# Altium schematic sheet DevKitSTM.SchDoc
size A2; PageSetup: Record=PageOptions¦CenterHorizontal=True¦CenterVertical=True¦PrintScale=0.52¦XCorrection=1.00¦YCorrection=1.00¦PrintKind=1¦BorderSize=5000000¦LeftOffset=0¦BottomOffset=0¦Orientation=2¦PaperLength=1000¦PaperWidth=1000¦Scale=100¦PaperSource=7¦PrintQuality=600¦MediaType=1¦DitherType=10¦PaperKind=A4¦PrintScaleMode=1
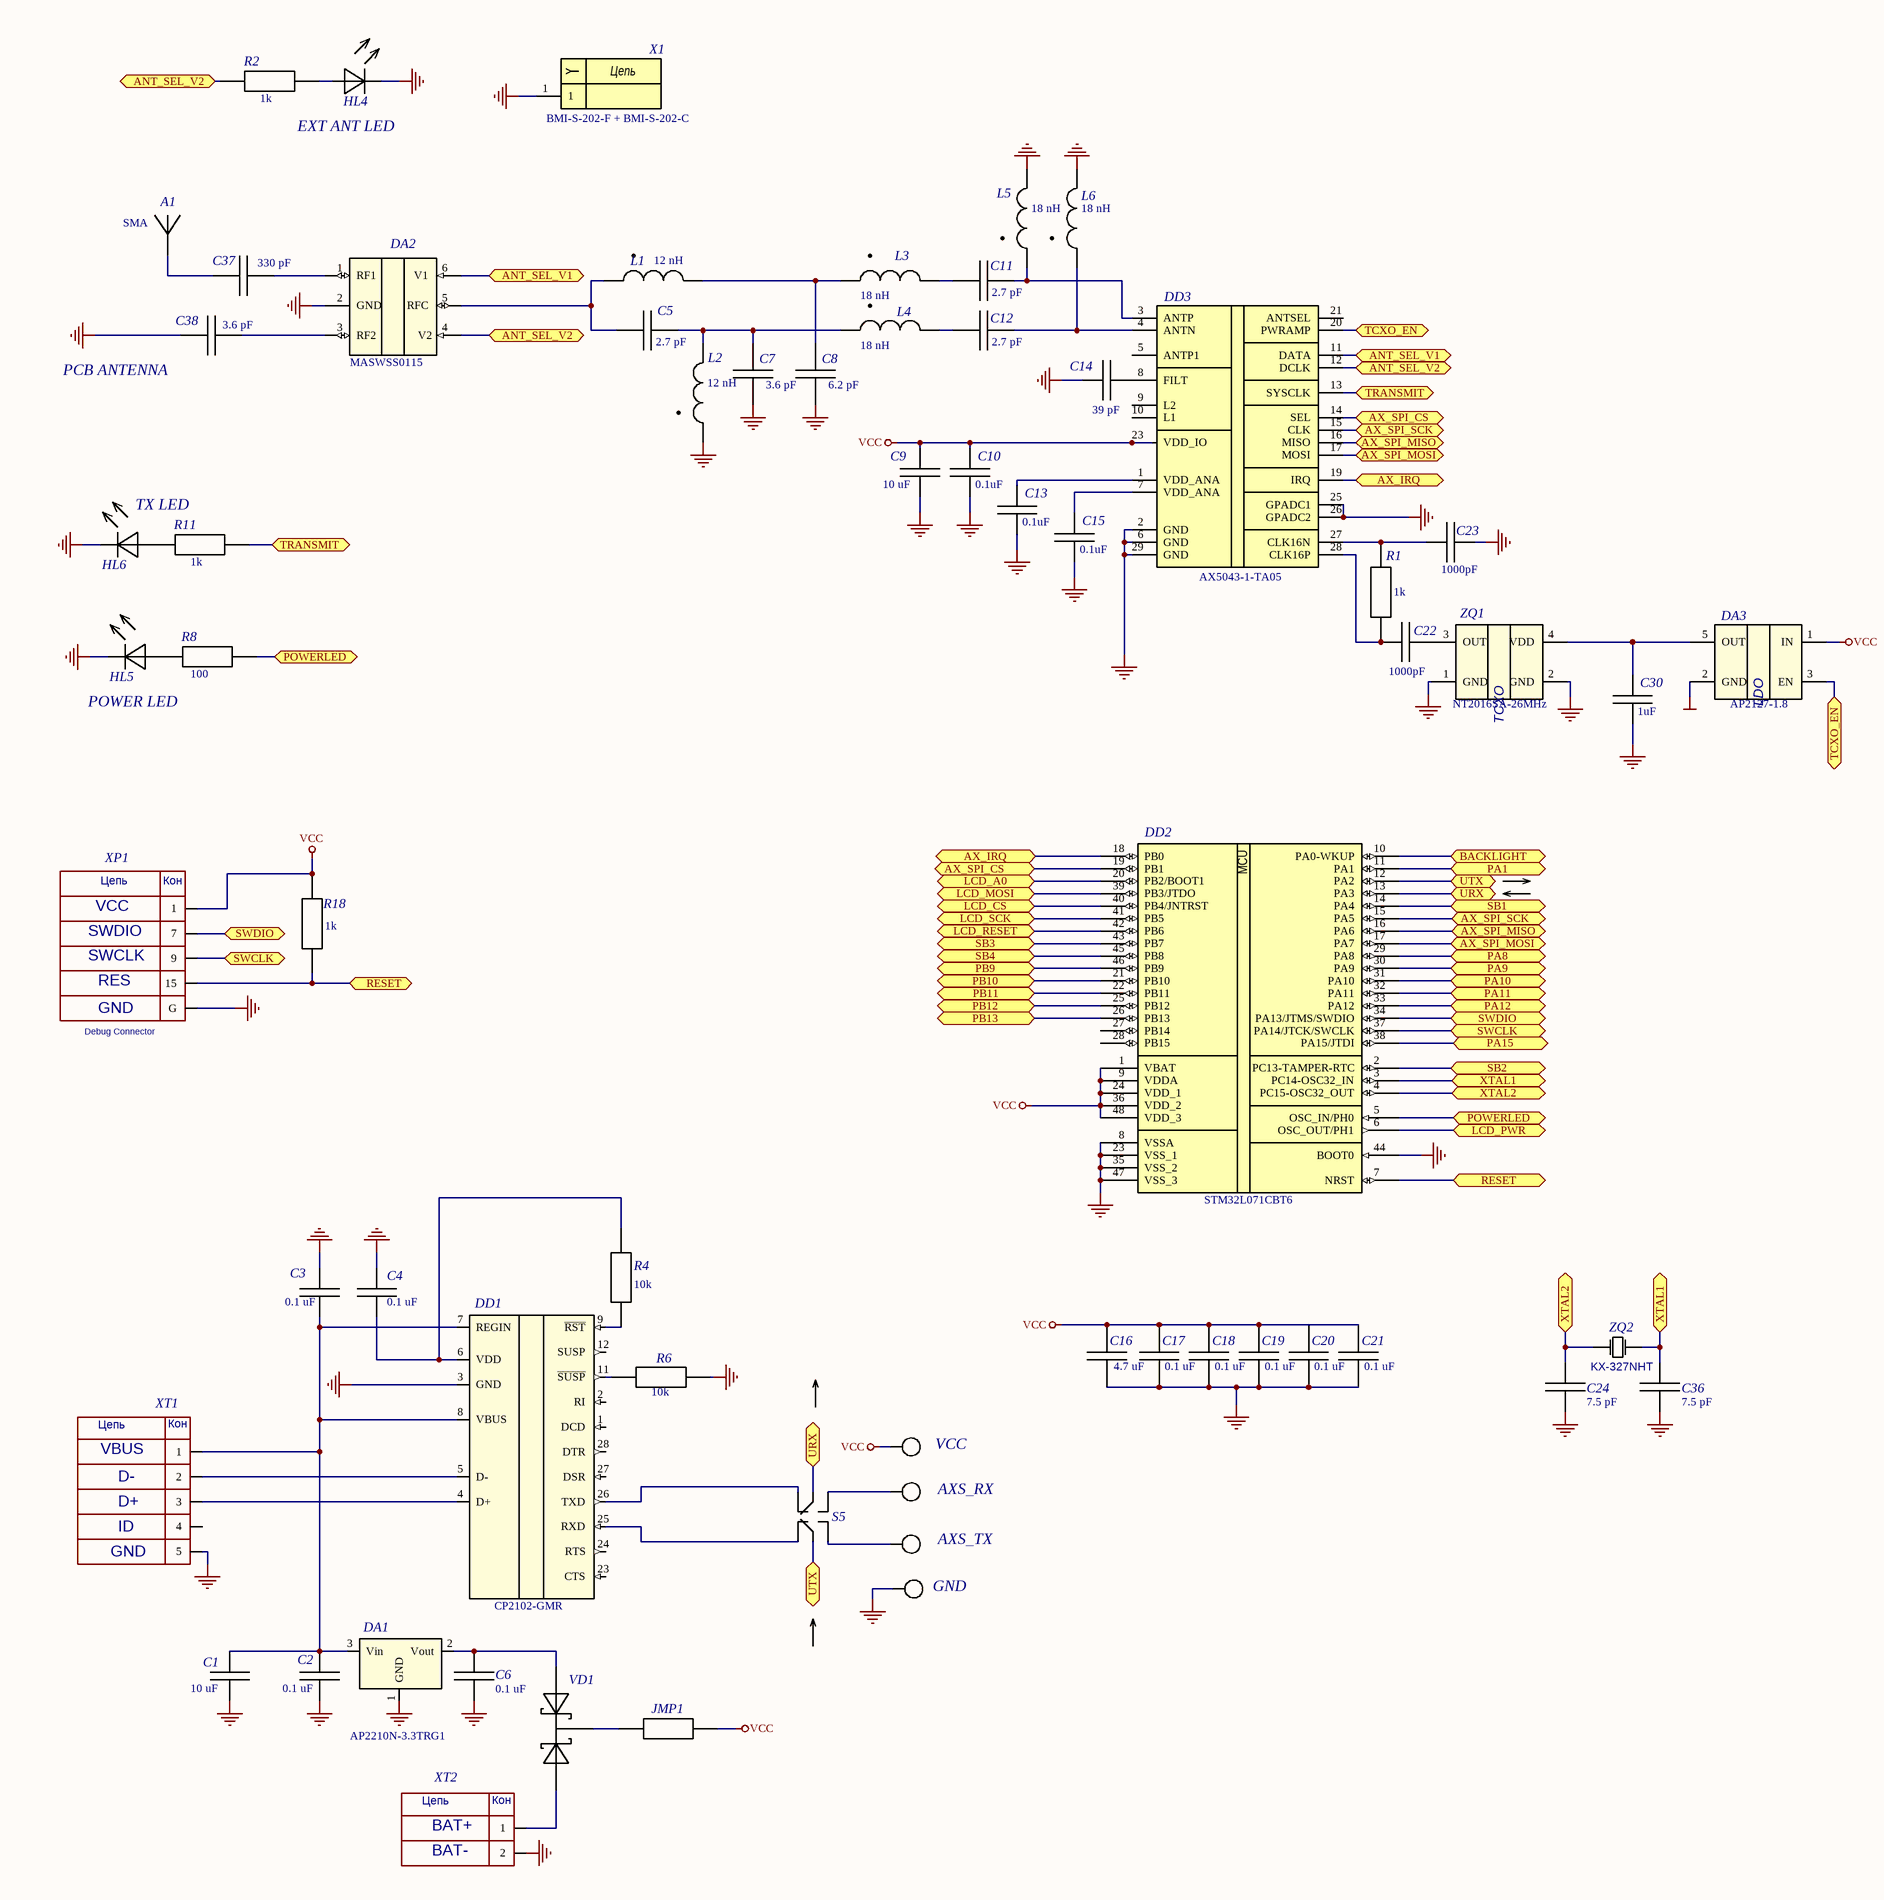
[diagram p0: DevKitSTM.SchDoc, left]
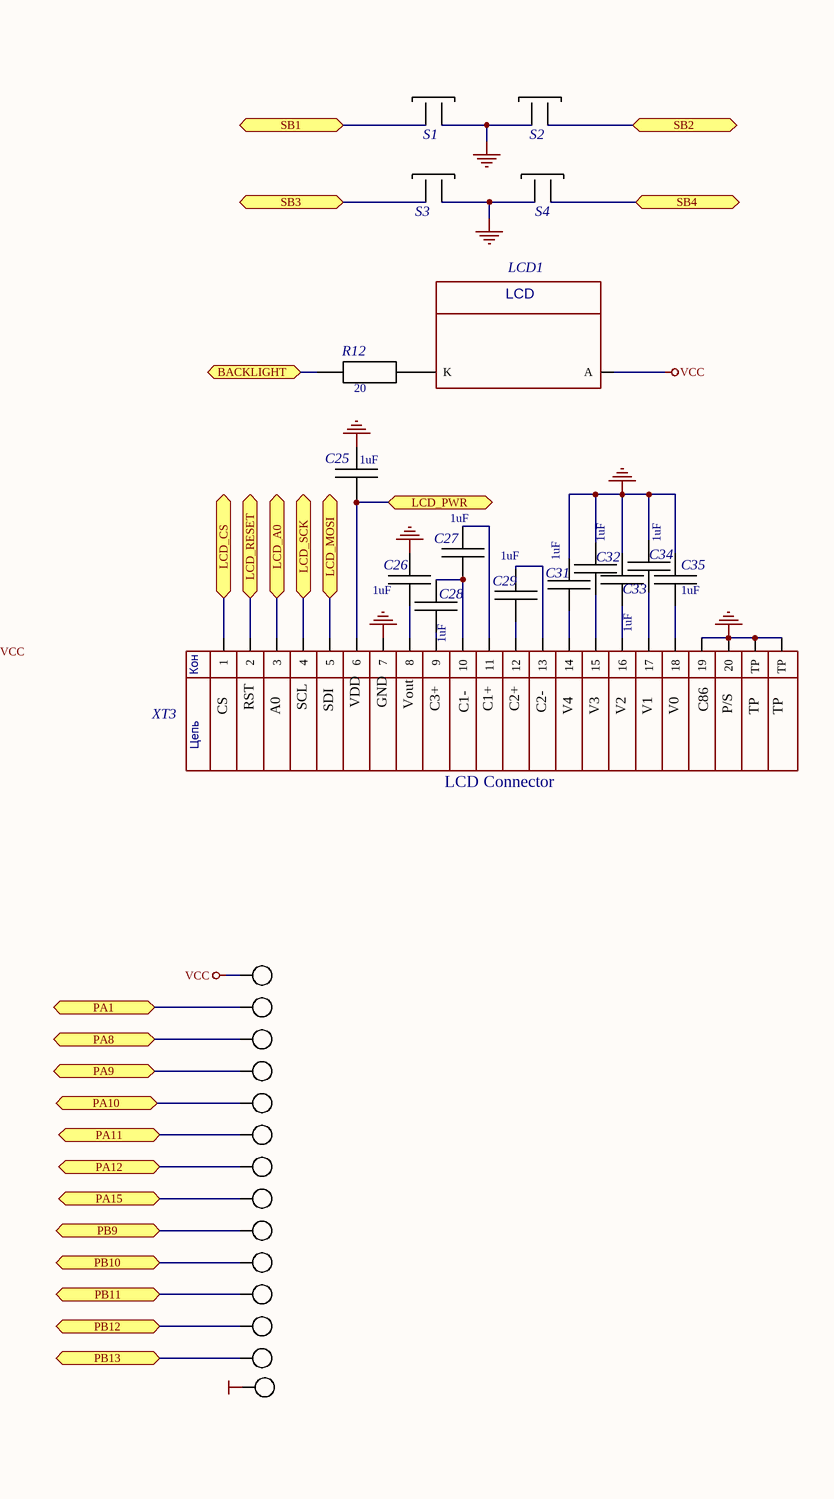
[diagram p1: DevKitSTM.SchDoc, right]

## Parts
A1  SMA  [SMA_Str]  (net tie, no BOM)
C1  10 uF  [Cap_1206]
C2  0.1 uF  [Cap_0603]
C3  0.1 uF  [Cap_0603]
C4  0.1 uF  [Cap_0603]
C5  value 2.7 pF  [CAP_0603]
C6  0.1 uF  [Cap_0603]
C7  value 3.6 pF  [CAP_0603]
C8  value 6.2 pF  [CAP_0603]
C9  10 uF  [Cap_1206]
C10  0.1uF  [Cap_0603]
C11  value 2.7 pF  [CAP_0603]
C12  value 2.7 pF  [CAP_0603]
C13  0.1uF  [Cap_0603]
C14  39 pF  [Cap_0603]
C15  0.1uF  [Cap_0603]
C16  value 4.7 uF  [CAP_0603]
C17  value 0.1 uF  [CAP_0603]
C18  value 0.1 uF  [CAP_0603]
C19  value 0.1 uF  [CAP_0603]
C20  value 0.1 uF  [CAP_0603]
C21  value 0.1 uF  [CAP_0603]
C22  1000pF  [Cap_0603]
C23  1000pF  [Cap_0603]
C24  7.5 pF  [Cap_0603]
C25  1uF  [Cap_0603]
C26  1uF  [Cap_0603]
C27  1uF  [Cap_0603]
C28  1uF  [Cap_0603]
C29  1uF  [Cap_0603]
C30  1uF  [Cap_0603]
C31  1uF  [Cap_0603]
C32  1uF  [Cap_0603]
C33  1uF  [Cap_0603]
C34  1uF  [Cap_0603]
C35  1uF  [Cap_0603]
C36  7.5 pF  [Cap_0603]
C37  value 330 pF  [CAP_0603]
C38  value 3.6 pF  [CAP_0603]
DA1  PartNumber: AP2210N-3.3TRG1  [SOT23_L]  (hidden comment: AP2210)
DA2  MASWSS0115  [SC-70]
DA3  AP2127-1.8  [SOT23-5AN]
DD1  PartNumber: CP2102-GMR  [QFN28]  (hidden comment: CP2102)
DD2  STM32L071CBT6  [TSQFP50P900X900X160-48N]
DD3  AX5043-1-TA05  [QFN28]
HL4  LED_0603  [led0603]  (value not drawn)
HL5  LED_0603  [led0603]  (value not drawn)
HL6  LED_0603  [led0603]  (value not drawn)
JMP1  STD_RES  [JMP_PCB]  (value not drawn)  (no BOM)
L1  value 12 nH  [IND_0603]  (hidden comment: STD_IND)
L2  value 12 nH  [IND_0603]  (hidden comment: STD_IND)
L3  value 18 nH  [IND_0603]  (hidden comment: STD_IND)
L4  value 18 nH  [IND_0603]  (hidden comment: STD_IND)
L5  value 18 nH  [IND_0603]  (hidden comment: STD_IND)
L6  value 18 nH  [IND_0603]  (hidden comment: STD_IND)
LCD1  LCD_JHD  [LCD_JHD]  (value not drawn)
R1  1k  [RES_0603]
R2  1k  [RES_0603]
R4  10k  [RES_0603]
R6  10k  [RES_0603]
R8  100  [RES_0603]
R11  1k  [RES_0603]
R12  20  [RES_0603]
R18  1k  [RES_0603]
S1  SMD Button  [FSM_Button]  (value not drawn)  (no BOM)
S2  SMD Button  [FSM_Button]  (value not drawn)  (no BOM)
S3  SMD Button  [FSM_Button]  (value not drawn)  (no BOM)
S4  SMD Button  [FSM_Button]  (value not drawn)  (no BOM)
S5  CAS-220  [CAS-220]  (value not drawn)  (no BOM)
VD1  PMEG2005CT  [SOT23]  (value not drawn)
X1  PartNumber: BMI-S-202-F + BMI-S-202-C  [BMI-S-202-F]  (hidden comment: STD_CON1)
XP1  Debug Connector  [BH-20]
XP2  PLS-1  [HDR1X1]  (value not drawn)
XP3  PLS-1  [HDR1X1]  (value not drawn)
XP4  PLS-1  [HDR1X1]  (value not drawn)
XP5  PLS-1  [HDR1X1]  (value not drawn)
XP6  PLS-1  [HDR1X1]  (value not drawn)
XP7  PLS-1  [HDR1X1]  (value not drawn)
XP8  PLS-1  [HDR1X1]  (value not drawn)
XP10  PLS-1  [HDR1X1]  (value not drawn)
XP11  PLS-1  [HDR1X1]  (value not drawn)
XP13  PLS-1  [HDR1X1]  (value not drawn)
XP14  PLS-1  [HDR1X1]  (value not drawn)
XP15  PLS-1  [HDR1X1]  (value not drawn)
XP16  PLS-1  [HDR1X1]  (value not drawn)
XP17  PLS-1  [HDR1X1]  (value not drawn)
XP21  PLS-1  [HDR1X1]  (value not drawn)
XP22  PLS-1  [HDR1X1]  (value not drawn)
XP23  PLS-1  [HDR1X1]  (value not drawn)
XP24  PLS-1  [HDR1X1]  (value not drawn)
XT1  Molex_MINIUSB  [Molex_MINIUSB]  (value not drawn)
XT2  Molex053047  [Molex0533980271]  (value not drawn)
XT3  Molex0527462071  [Molex_0527462071]  (value not drawn)
ZQ1  NT2016SA-26MHz  [NT2016SA]
ZQ2  KX-327NHT  [KX-327NHT]

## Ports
ANT_SEL_V1, ANT_SEL_V2, AX_IRQ, AX_SPI_CS, AX_SPI_MISO, AX_SPI_MOSI, AX_SPI_SCK, BACKLIGHT, LCD_A0, LCD_CS, LCD_MOSI, LCD_PWR, LCD_RESET, LCD_SCK, PA1, PA8, PA9, PA10, PA11, PA12, PA15, PB9, PB10, PB11, PB12, PB13, POWERLED, RESET, SB1, SB2, SB3, SB4, SWCLK, SWDIO, TCXO_EN, TRANSMIT, URX, UTX, XTAL1, XTAL2

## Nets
GND: A1.2 C1.1 C2.2 C3.2 C6.2 C7.2 C8.2 C9.1 C10.1 C13.1 C14.1 C15.1 C16.2 C17.2 C18.2 C19.2 C20.2 C21.2 C23.2 C24.1 C25.2 C26.2 C30.1 C31.2 C32.2 C33.2 C34.2 C35.2 C36.1 C38.1 DA1.1(GND) DA2.2(GND) DA3.2(GND) DD2.8(VSSA) DD2.23(VSS_1) DD2.35(VSS_2) DD2.44(BOOT0) DD2.47(VSS_3) DD3.2(GND) DD3.6(GND) DD3.25(GPADC1) DD3.26(GPADC2) DD3.29(GND) HL4.C HL5.C HL6.C L2.1 L5.2 L6.2 R6.1 S1.2 S2.2 S3.2 S4.2 X1.1 XP1.G XP17.1 XP24.1 XT1.5 XT2.2 XT3.7 XT3.19 XT3.20 XT3.21(TP) XT3.22(TP) ZQ1.1(GND) ZQ1.2(GND)
NetC4_2: C4.2 DD1.3(GND)
VCC: C9.2 C10.2 C16.1 C17.1 C18.1 C19.1 C20.1 C21.1 DA3.1(IN) DD2.1(VBAT) DD2.9(VDDA) DD2.24(VDD_1) DD2.36(VDD_2) DD2.48(VDD_3) DD3.23(VDD_IO) JMP1.2 LCD1.A R18.2 XP1.1 XP13.1 XP21.1
ANT_SEL_V1: DA2.6(V1) DD3.11(DATA) ; port ANT_SEL_V1
ANT_SEL_V2: DA2.4(V2) DD3.12(DCLK) R2.1 ; port ANT_SEL_V2
AX_IRQ: DD2.18(PB0) DD3.19(IRQ) ; port AX_IRQ
AX_SPI_CS: DD2.19(PB1) DD3.14(SEL) ; port AX_SPI_CS
AX_SPI_MISO: DD2.16(PA6) DD3.16(MISO) ; port AX_SPI_MISO
AX_SPI_MOSI: DD2.17(PA7) DD3.17(MOSI) ; port AX_SPI_MOSI
AX_SPI_SCK: DD2.15(PA5) DD3.15(CLK) ; port AX_SPI_SCK
BACKLIGHT: DD2.10(PA0-WKUP) R12.1 ; port BACKLIGHT
LCD_A0: DD2.20(PB2/BOOT1) XT3.3 ; port LCD_A0
LCD_CS: DD2.40(PB4/JNTRST) XT3.1 ; port LCD_CS
LCD_MOSI: DD2.39(PB3/JTDO) XT3.5 ; port LCD_MOSI
LCD_PWR: C25.1 DD2.6(OSC_OUT/PH1) XT3.6 ; port LCD_PWR
LCD_RESET: DD2.42(PB6) XT3.2 ; port LCD_RESET
LCD_SCK: DD2.41(PB5) XT3.4 ; port LCD_SCK
PA1: DD2.11(PA1) XP14.1 ; port PA1
PA8: DD2.29(PA8) XP10.1 ; port PA8
PA9: DD2.30(PA9) XP15.1 ; port PA9
PA10: DD2.31(PA10) XP11.1 ; port PA10
PA11: DD2.32(PA11) XP5.1 ; port PA11
PA12: DD2.33(PA12) XP6.1 ; port PA12
PA15: DD2.38(PA15/JTDI) XP7.1 ; port PA15
PB9: DD2.46(PB9) XP2.1 ; port PB9
PB10: DD2.21(PB10) XP3.1 ; port PB10
PB11: DD2.22(PB11) XP4.1 ; port PB11
PB12: DD2.25(PB12) XP8.1 ; port PB12
PB13: DD2.26(PB13) XP16.1 ; port PB13
POWERLED: DD2.5(OSC_IN/PH0) R8.1 ; port POWERLED
RESET: DD2.7(NRST) R18.1 XP1.15 ; port RESET
SB1: DD2.14(PA4) S1.1 ; port SB1
SB2: DD2.2(PC13-TAMPER-RTC) S2.1 ; port SB2
SB3: DD2.43(PB7) S3.1 ; port SB3
SB4: DD2.45(PB8) S4.1 ; port SB4
SWCLK: DD2.37(PA14/JTCK/SWCLK) XP1.9 ; port SWCLK
SWDIO: DD2.34(PA13/JTMS/SWDIO) XP1.7 ; port SWDIO
TCXO_EN: DA3.3(EN) DD3.20(PWRAMP) ; port TCXO_EN
TRANSMIT: DD3.13(SYSCLK) R11.1 ; port TRANSMIT
URX: DD2.13(PA3) S5.2 ; port URX
UTX: DD2.12(PA2) S5.5 ; port UTX
XTAL1: C36.2 DD2.3(PC14-OSC32_IN) ZQ2.1 ; port XTAL1
XTAL2: C24.2 DD2.4(PC15-OSC32_OUT) ZQ2.2 ; port XTAL2
NetA1_1: A1.1 C37.1
NetC1_2: C1.2 C2.1 C3.1 DA1.3(Vin) DD1.7(REGIN) DD1.8(VBUS) XT1.1
NetC4_1: C4.1 DD1.6(VDD) R4.2
NetC5_1: C5.1 DA2.5(RFC) L1.1
NetC5_2: C5.2 C7.1 L2.2 L4.1
NetC6_1: C6.1 DA1.2(Vout) VD1.2(A)
NetC8_1: C8.1 L1.2 L3.1
NetC11_1: C11.1 L3.2
NetC11_2: C11.2 DD3.3(ANTP) L5.1
NetC12_1: C12.1 L4.2
NetC12_2: C12.2 DD3.4(ANTN) L6.1
NetC13_2: C13.2 DD3.1(VDD_ANA)
NetC14_2: C14.2 DD3.8(FILT)
NetC15_2: C15.2 DD3.7(VDD_ANA)
NetC22_1: C22.1 DD3.28(CLK16P) R1.1
NetC22_2: C22.2 ZQ1.3(OUT)
NetC23_1: C23.1 DD3.27(CLK16N) R1.2
NetC26_1: C26.1 XT3.8
NetC27_1: C27.1 XT3.11
NetC27_2: C27.2 C28.2 XT3.10
NetC28_1: C28.1 XT3.9
NetC29_1: C29.1 XT3.12
NetC29_2: C29.2 XT3.13
NetC30_2: C30.2 DA3.5(OUT) ZQ1.4(VDD)
NetC31_1: C31.1 XT3.14
NetC32_1: C32.1 XT3.15
NetC33_1: C33.1 XT3.16
NetC34_1: C34.1 XT3.17
NetC35_1: C35.1 XT3.18
NetC37_2: C37.2 DA2.1(RF1)
NetC38_2: C38.2 DA2.3(RF2)
NetDD1_4: DD1.4(D+) XT1.3
NetDD1_5: DD1.5(D-) XT1.2
NetDD1_9: DD1.9(~{RST}) R4.1
NetDD1_11: DD1.11(~{SUSP}) R6.2
NetDD1_25: DD1.25(RXD) S5.6
NetDD1_26: DD1.26(TXD) S5.3
NetHL4_A: HL4.A R2.2
NetHL5_A: HL5.A R8.2
NetHL6_A: HL6.A R11.2
NetJMP1_1: JMP1.1 VD1.3(C)
NetLCD1_K: LCD1.K R12.2
NetS5_1: S5.1 XP22.1
NetS5_4: S5.4 XP23.1
NetVD1_1: VD1.1(A) XT2.1

Not connected (* = marked no-connect by the designer): DD1 1(DCD) 2(RI) 12(SUSP) 23(CTS) 24(RTS) 27(DSR) 28(DTR); DD2 27(PB14) 28(PB15); DD3 5(ANTP1) 9(L2) 10(L1) 21(ANTSEL); XT1 4

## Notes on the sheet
- EXT ANT LED
- PCB ANTENNA
- TX LED
- POWER LED
- CS
- RST
- A0
- SCL
- SDI
- VDD
- GND
- Vout
- C3+
- C1-
- C1+
- C2+
- C2-
- V4
- V3
- V2
- V1
- V0
- C86
- P/S
- TP
- LCD Connector
- VCC
- AXS_RX
- (near XP24) GND
- AXS_TX
- (near XT2) BAT+
- (near XT2) BAT-

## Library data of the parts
A1 = SMA_Str: CONN SMA JACK STR 50 OHM PCB; PartNumber: 5-1814832-1
C1 C9 = Cap 1206: CAP CER 10UF 16V Y5V 1206; PartNumber: CL31F106ZOHNNNE; Dezigner: Kharlamov M V; Code Value: code of resistance marked on chip
C2-C4 C6 C10 C13 C15 = Cap 0603: CAP CER 0603 0.1 uF 16 V 10% X7R; PartNumber: CC0603KRX7R7BB104; BSPId: ГОСТ 2.728-74 УГО конденсаторы; Dezigner: Kharlamov M V; Code Value: code of resistance marked on chip; Note: Ваши примечания
C5 C11 C12 = GRM1885C1H2R7CA01D: CAP CER 2.7PF 50V NPO 0603; PartNumber: CC0603BRNPO9BN2R7; Manufacturer: MURATA; ID: 176; Tolerance: +/- 0.25 пФ; Напряжение: 50 В; Температура: -55...+85°C; Autor: Admin
C7 C38 = CL10C3R6CB8NNNC: CAP CER 3.6PF 50V NPO 0603; PartNumber: CC0603BRNPO9BN3R6; Manufacturer: Samsung; ID: 177; Tolerance: +/- 0.25 пФ; Напряжение: 50 В; Температура: -55...+85°C; Autor: Admin
C8 = CL10C6R2CB8NNNC: CAP CER 6.2PF 50V NPO 0603; Manufacturer: Samsung; ID: 178; Tolerance: +/- 0.25 пФ; Напряжение: 50 В; Температура: -55...+85°C; Autor: Admin
C14 = Cap 0603: CAP CER 39PF 50V C0G/NPO 0603; PartNumber: CC0603JRNPO9BN390; BSPId: ГОСТ 2.728-74 УГО конденсаторы; Dezigner: Kharlamov M V; Code Value: code of resistance marked on chip; Note: Ваши примечания
C16 = CC0603KRX5R6BB475: CAP CER 0603 4.7 uF 10 V 10% X5R; Manufacturer: YAGEO; ID: 71; Напряжение: 10 В; Температура: -55...+85°C; Autor: Цислав А.Н.
C17-C21 = CC0603KRX7R7BB104: CAP CER 0603 0.1 uF 16 V 10% X7R; Manufacturer: YAGEO; ID: 27; Напряжение: 16 В; Температура: -55...+85°C; Autor: Admin
C22 C23 = Cap 0603: CAP CER 1000PF 50V X7R 0603; PartNumber: CC0603KRX7R9BB102; BSPId: ГОСТ 2.728-74 УГО конденсаторы; Dezigner: Kharlamov M V; Code Value: code of resistance marked on chip; Note: Ваши примечания
C24 C36 = Cap 0603: CAP CER 7.5PF 50V NPO 0603; PartNumber: CC0603CRNPO9BN7R5; BSPId: ГОСТ 2.728-74 УГО конденсаторы; Dezigner: Kharlamov M V; Code Value: code of resistance marked on chip; Note: Ваши примечания
C25-C29 C31-C35 = Cap 0805: CAP CER 1UF 16V X7R 0603; PartNumber: CC0603KRX7R7BB105; Dezigner: Kharlamov M V; Code Value: code of resistance marked on chip
C30 = Cap 0603: CAP CER 1UF 16V X7R 0603; PartNumber: CC0603KRX7R7BB105; BSPId: ГОСТ 2.728-74 УГО конденсаторы; Dezigner: Kharlamov M V; Code Value: code of resistance marked on chip; Note: Ваши примечания
C37 = GRM1885C1H2R7CA01D: CAP CER 330PF 50V NPO 0603; PartNumber: CC0603JRNPO9BN331; Manufacturer: MURATA; ID: 176; Tolerance: +/- 0.25 пФ; Напряжение: 50 В; Температура: -55...+85°C; Autor: Admin
DA1 = AP2210: IC REG LDO 3.3V 0.3A SOT23; Comment_1: TPS61040
DA2 = MASWSS0115: GaAs SPDT Switch  DC - 3.0 GHz; PartNumber: MASWSS0115TR-3000
DA3 = AP2127: IC REG LINEAR 1.8V 300MA SOT23-5; PartNumber: AP2127K-1.8TRG1; Comment_1: TPS61040
DD1 = CP2102: IC USB-TO-UART BRIDGE 28VQFN
DD2 = STM32_LQFP48: IC MCU 32BIT 128KB FLASH 48LQFP; Manufacturer: STMicroelectronics; Core Processor: ARM® Cortex®-M0+; Core Size: 32-Bit; Speed: 32MHz; Connectivity: I²C, IrDA, SPI, UART/USART; Peripherals: Brown-out Detect/Reset, DMA, POR, PWM, WDT; Number of I/O: 37; Program Memory Size: 128KB (128K x 8); EEPROM Size: 6K x 8; RAM Size: 20K x 8; Voltage - Supply (Vcc/Vdd): 1.65 V ~ 3.6 V; Data Converters: A/D 13x12b; Oscillator Type: Internal
DD3 = AX5043: IC AXSEM RF Tranceiver
HL4 = LED_0603: LED GREEN CLEAR 0603 SMD; PartNumber: APT1608CGCK
HL5 = LED_0603: LED 527NM BLU/GRN TRANSP RA SMD; PartNumber: SMLE13EC8TT86
HL6 = LED_0603: LED 1.6X0.8MM 630NM RED CLR SMD; PartNumber: APT1608SURCK
JMP1 = JMP_PCB: NoName  PCB Jumper; ID: 46; Температура: -40...+85°C; Autor: Admin
L1 = LQW18AN12NG00: FIXED IND 18NH 650MA 160 MOHM; Manufacturer: MURATA; ID: 105; Type: CHIP-0603_RF; Tolerance: 2%; Current: 650 мА; Температура: -40...+85°C; Autor: Цислав А.Н.
L2 = LQW18AN12NG00: FIXED IND 12NH 650MA 160 MOHM; Manufacturer: MURATA; ID: 105; Type: CHIP-0603_RF; Tolerance: 2%; Current: 650 мА; Температура: -40...+85°C; Autor: Цислав А.Н.
L3-L6 = LQW18AN18NG00: FIXED IND 18NH 550MA 160 MOHM; Manufacturer: MURATA; ID: 87; Type: CHIP-0603_RF; Tolerance: 2%; Current: 500 мА; Температура: -40...+85°C; Autor: Цислав А.Н.
LCD1 = LCD_JHD: LCD Display; PartNumber: JHD12864
R1 R2 R11 R18 = Res 0603: RES SMD 1K OHM 1% 1/10W 0603; PartNumber: RC1608F102CS; BSPId: ГОСТ 2.728-74 УГО резисторы; Note: Ваши примечания; Dezigner: Kharlamov M V; ModelName: RESC1005X04L (0402); Code Value: code of resistance marked on chip
R4 R6 = Res 0603: RES SMD 10 KOHM 1% 1/10W 0603; PartNumber: RC1608F103CS; BSPId: ГОСТ 2.728-74 УГО резисторы; Note: Ваши примечания; Dezigner: Kharlamov M V; ModelName: RESC1005X04L (0402); Code Value: code of resistance marked on chip
R8 = Res 0603: RES SMD 100 OHM 1% 1/10W 0603; PartNumber: RC1608J101CS; BSPId: ГОСТ 2.728-74 УГО резисторы; Note: Ваши примечания; Dezigner: Kharlamov M V; ModelName: RESC1005X04L (0402); Code Value: code of resistance marked on chip
R12 = Res 0805: RES SMD 20 OHM 1% 1/10W 0603; PartNumber: RC1608F200CS; BSPId: ГОСТ 2.728-74 УГО резисторы; Note: Ваши примечания; Dezigner: Kharlamov M V; ModelName: RESC1005X04L (0402); Code Value: code of resistance marked on chip
S1-S4 = SMD Button: SWITCH TACTILE SPST-NO 0.05A 24V; PartNumber: FSM4JSMATR
S5 = CAS-220: SLIDE SWITCH DPDT GULLWING 6V; PartNumber: CAS-220TB
VD1 = PMEG2005CT: DIODE ARRAY SCHOTTKY 20V SOT23; Manufacturer: NXP; ID: 31; Type: Diode Schottky; U_direct: 500 мВ; U_reverse: 20 В; Current: 500 мА; Температура: -40...+85°C; Autor: Admin
X1 = BMI-S-202-F: BOARD SHIELD .65X.65" FRAME + COVER; Manufacturer: Liard; ID: 46; Contact: 1; Autor: Цислав А.Н.
XP1 = JTAG_BH20: CONN 2 RAWS 20 PINS 2.54 PITCH
XT1 = Molex_MINIUSB: CONN RECEPT MINIUSB R/A 5POS SMD; PartNumber: 548190572
XT2 = Molex053047: CONN HEADER 2POS 1.25MM VERT SMD; PartNumber: 533980271
XT3 = Molex0527462071: 20-pin LCD connector; PartNumber: CONN_FOR_JHD12864
ZQ1 = NT2016: Quartz Crystal Controlled Oscillator; PartNumber: NT2016SA-26.000000MHZ-NBG2; Comment_1: TPS61040
ZQ2 = KX-327NHT: Geyer  Quartz Crystal; Part Manufacturer: GEYER ELECTRONIC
